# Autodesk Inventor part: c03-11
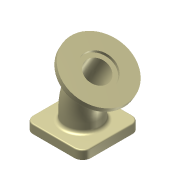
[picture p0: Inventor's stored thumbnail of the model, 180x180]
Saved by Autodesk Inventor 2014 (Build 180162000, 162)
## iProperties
Created: 2011-11
Part Number: c03-11
Material: Iron, Cast
Document SubType Name: Modeling
Designer: Thom Tremblay
Density: 7.25 g/cm^3
Mass: 1087.5 g
Surface Area: 260 cm^2
Volume: 150 cm^3
Appearance: Nylon 6
Author: Thom Tremblay
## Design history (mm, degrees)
sketch "Sketch1"
  geometry: L1 (50, -50)-(-50, -50); L2 (-50, -50)-(-50, 50); L3 (-50, 50)-(50, 50); L4 (50, 50)-(50, -50); C1 r 20 at (0, 0); C2 r 30 at (0, 0); 3 further points
  constraints: 8 end point, 2 centre point, 2 coincident, 2 midpoint, 2 parallel, 2 perpendicular, 1 horizontal, 1 horizontal alignment, 1 vertical alignment
  dimensions: "d0" = 100 distance of L2.end L3.end; "d3" = 40 diameter of C1; "d4" = 10 radial gap between concentric circles of C2 C1
extrude "Extrusion1" new body sketch "Sketch1" distance "d1" = 15; taper "d2" = 0 deg
sketch "Sketch2"
  geometry: L1 (0, 0)-(0, 30); L2 (12.794, 77.746)-(27.794, 103.727); A1 r 95.493 centre (95.493, 30) between (12.794, 77.746) and (0, 30)
  constraints: 4 end point, 2 point on circle, 2 tangent, 1 centre point, 1 vertical
  dimensions: "d5" = 30 distance of L1.start L1.end; "d7" = 50 dimension on A1; "d9" = 30 distance of L2.start L2.end; "d10" = 30 deg angle of L2 L1
sketch "Sketch3"
  geometry: L1 (12.794, 77.746)-(27.794, 103.727) reference; L2 (27.794, 103.727)-(75.425, 76.227); L3 (75.425, 76.227)-(70.425, 67.567); L4 (70.425, 67.567)-(22.794, 95.067); L5 (22.794, 95.067)-(27.794, 103.727); 2 further points
  constraints: 8 end point, 2 parallel, 2 perpendicular
  dimensions: "d11" = 110 diameter of L3 L5; "d13" = 10 distance between parallel lines of L2 L4
revolve "Revolution1" sketch "Sketch3" stored, may be unused: angle "d14" = 90 deg
sweep "Sweep1" dims "d15" = 0
sweep "Sweep2" dims "d16" = 0
sketch "Sketch4"
  geometry: C1 r 55 at (0, 0) reference; C2 r 27.5 at (0, 0); 1 further point
  constraints: 1 centre point, 1 coincident
  dimensions: "d17" = 55 diameter of C2
extrude "Extrusion2" cut sketch "Sketch4" distance "d18" = 5; taper "d19" = 0 deg
fillet "Fillet1" dims "d20" = 14
fillet "Fillet2" dims "d21" = 6, "d22" = 2
body "Solid1"
